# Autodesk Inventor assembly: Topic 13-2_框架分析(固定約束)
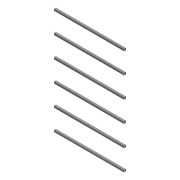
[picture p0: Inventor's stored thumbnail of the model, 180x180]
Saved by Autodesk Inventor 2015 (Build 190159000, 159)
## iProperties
Created: 2020-03
Part Number: Topic 13-2_框架分析(固定約束)
Document SubType Name: Assembly
Designer: 徐冠倫
Mass: 14532.6 g
Surface Area: 12379 cm^2
Volume: 1851.29 cm^3
Density: 7.85 g/cm^3
_SolveAssemblyDoc: Frame Generator Solve Assembly
_Version: 15.0.0
Author: 徐冠倫
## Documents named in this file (4)
- C:\Users\徐冠倫\Desktop\Topic 12-2_框架分析(固定約束)\Topic 12-2_框架分析(固定約束).iam
- Topic 12-2_框架分析(固定約束).iam
- C:\Users\徐冠倫\Desktop\Topic 12-2_框架分析(固定約束)\Topic 12-2_框架分析(固定約束).ipt
- C:\Users\徐冠倫\Desktop\Topic 12-2_框架分析(固定約束)\Topic 12-2_框架分析(固定約束)\Frame\Frame0001.iam
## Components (7 placed, 2 different names)
1. Topic 12-2_框架分析(固定約束):1
2. Frame0001:1 [sub-assembly]
3. Frame0001:2 [sub-assembly]
4. Frame0001:3 [sub-assembly]
5. Frame0001:4 [sub-assembly]
6. Frame0001:5 [sub-assembly]
7. Frame0001:6 [sub-assembly]
